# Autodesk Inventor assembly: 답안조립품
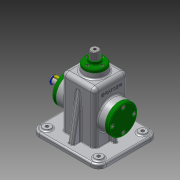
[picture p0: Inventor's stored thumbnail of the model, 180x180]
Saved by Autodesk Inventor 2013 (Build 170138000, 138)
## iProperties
Created: 2016-06
Part Number: 답안조립품
Document SubType Name: Assembly
Designer: home
Author: home
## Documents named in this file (18)
- C:\Users\home\Desktop\Manufacturing2급-홍성기\답안조립품.iam
- C:\Users\home\Desktop\Manufacturing2급-홍성기\본체.ipt
- C:\Users\home\Desktop\Manufacturing2급-홍성기\공용부품\앞커버.ipt
- C:\Users\home\Desktop\Manufacturing2급-홍성기\공용부품\뒤커버.ipt
- C:\Users\home\Desktop\Manufacturing2급-홍성기\공용부품\베어링 15 x 35 x 11.ipt
- C:\Users\home\Desktop\Manufacturing2급-홍성기\공용부품\편심축.ipt
- C:\Users\home\Desktop\Manufacturing2급-홍성기\공용부품\상부부시.ipt
- C:\Users\home\Desktop\Manufacturing2급-홍성기\공용부품\멈춤링 15 x 1.ipt
- C:\Users\home\Desktop\Manufacturing2급-홍성기\공용부품\오일실 15 25 7.ipt
- C:\Users\home\Desktop\Manufacturing2급-홍성기\공용부품\와셔.ipt
- C:\Users\home\Desktop\Manufacturing2급-홍성기\공용부품\볼트 M6 x 12.ipt
- C:\Users\home\Desktop\Manufacturing2급-홍성기\공용부품\키 5 x 5 x 14.ipt
- C:\Users\home\Desktop\Manufacturing2급-홍성기\공용부품\링크.ipt
- C:\Users\home\Desktop\Manufacturing2급-홍성기\공용부품\슬라이드바.ipt
- C:\Users\home\Desktop\Manufacturing2급-홍성기\공용부품\고정핀.ipt
- C:\Users\home\Desktop\Manufacturing2급-홍성기\공용부품\멈춤링 6 x 5.ipt
- C:\Users\home\Desktop\Manufacturing2급-홍성기\공용부품\볼트 M4 x 10.ipt
- C:\Users\home\Desktop\Manufacturing2급-홍성기\공용부품\볼트 M3 x 8.ipt
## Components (14 placed, 4 different names)
1. 고정핀:1
2. ISO 4018 M6 x 12:1
3. ISO 4762 M4 x 10:1
4. ISO 4762 M4 x 10:3
5. ISO 4762 M4 x 10:4
6. ISO 4762 M4 x 10:5
7. ISO 4762 M4 x 10:2
8. ISO 4762 M4 x 10:6
9. ISO 4762 M4 x 10:7
10. ISO 4762 M4 x 10:8
11. ISO 4762 M3 x 8:1
12. ISO 4762 M3 x 8:2
13. ISO 4762 M3 x 8:3
14. ISO 4762 M3 x 8:4
